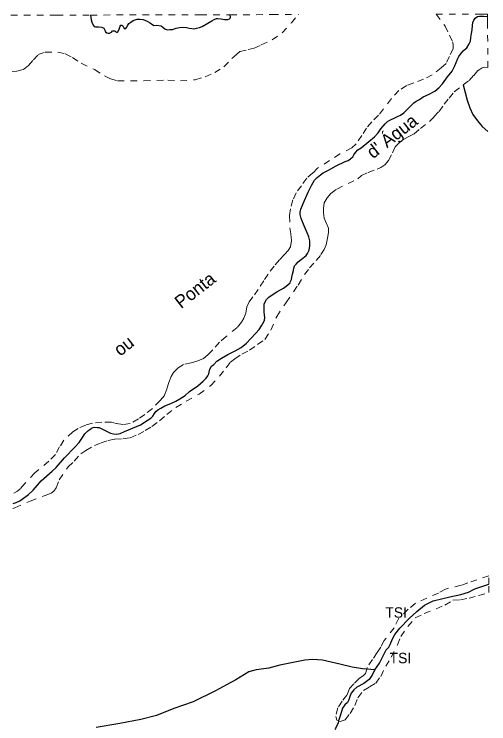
# Model space of a CAD drawing. Extents: x 391.8 to 446, y 8452 to 8507.5.
# Drawn here: x 438.61 to 445.91, y 8496.58 to 8507.5 of the extents above; entities that cross this region are included whole.
import ezdxf
from ezdxf.enums import TextEntityAlignment as Align

# ---------------------------------------------------------------- set-up
doc = ezdxf.new("R2010")
doc.units = 0
doc.header["$LTSCALE"] = 0.064
doc.linetypes.add('LONG_DASHED', pattern=[7.5, 6, -1.5])
doc.linetypes.add('SHORT_DASHED', pattern=[2.7, 1.5, -1.2])
for name, color, linetype, lineweight in [('21', 7, 'SHORT_DASHED', 13), ('62', 7, 'SHORT_DASHED', 13), ('63', 7, 'Continuous', 13), ('7', 7, 'Continuous', 25), ('9', 7, 'LONG_DASHED', 25)]:
    doc.layers.add(name, color=color, linetype=linetype, lineweight=lineweight)
doc.layers.add('61', color=7, linetype='Continuous')

msp = doc.modelspace()

# ---------------------------------------------------------------- linework, layer by layer
at = {"layer": '21'}
for points in [[(438.5766, 8506.6135), (438.6473, 8506.6199), (438.7501, 8506.6456), (438.8273, 8506.7098), (438.9044, 8506.7932), (438.9751, 8506.8767), (439.0844, 8506.9152), (439.2773, 8506.9152), (439.393, 8506.8895), (439.5023, 8506.8317), (439.6373, 8506.7419), (439.843, 8506.6456), (439.9972, 8506.5493), (440.0872, 8506.5043), (440.1965, 8506.4722), (440.6015, 8506.4722), (440.9718, 8506.4832), (441.1646, 8506.4704), (441.3896, 8506.4896), (441.5439, 8506.5346), (441.6918, 8506.5988), (441.8332, 8506.6887), (441.9553, 8506.8171), (442.027, 8506.8772), (442.0784, 8506.9222), (442.207, 8506.9543), (442.297, 8506.9735), (442.4063, 8507.0249), (442.5734, 8507.1019), (442.7277, 8507.2111), (442.8691, 8507.3651), (442.9794, 8507.4914)], [(445.0949, 8507.4959), (445.2327, 8507.3148), (445.2985, 8507.1761), (445.3497, 8507.0739), (445.357, 8507.0374), (445.357, 8506.9644), (445.2985, 8506.8476), (445.2474, 8506.7381), (445.1743, 8506.6724), (445.0354, 8506.5629), (444.9038, 8506.4972), (444.7504, 8506.4389), (444.6407, 8506.4024), (444.5238, 8506.3221), (444.4068, 8506.198), (444.2095, 8505.9425), (444.1072, 8505.8403), (444.0268, 8505.7454), (443.9537, 8505.6286), (443.866, 8505.5045), (443.7993, 8505.4419), (443.6166, 8505.347), (443.4558, 8505.2448), (443.2731, 8505.128), (443.2, 8505.055), (443.105, 8504.9747), (443.0246, 8504.8579), (442.9442, 8504.7484), (442.893, 8504.639), (442.8565, 8504.5003), (442.8419, 8504.3981), (442.8477, 8504.2122), (442.8623, 8504.1173), (442.8696, 8504.0151), (442.855, 8503.9202), (442.8184, 8503.8618), (442.76, 8503.7961), (442.6869, 8503.7158), (442.6065, 8503.621), (442.5115, 8503.4969), (442.4457, 8503.3947), (442.358, 8503.2633), (442.2776, 8503.1465), (442.2191, 8503.0735), (442.1826, 8502.9932), (442.1679, 8502.8983), (442.1387, 8502.818), (442.1022, 8502.7596), (442.0364, 8502.6793), (441.8678, 8502.5371), (441.7655, 8502.4495), (441.6632, 8502.3327), (441.5901, 8502.2597), (441.5097, 8502.194), (441.4147, 8502.1575), (441.327, 8502.1356), (441.21, 8502.1064), (441.1296, 8502.0553), (441.0565, 8501.9823), (441.02, 8501.9239), (440.9834, 8501.8291), (440.9542, 8501.7269), (440.9177, 8501.632), (440.8519, 8501.5517), (440.7318, 8501.4314), (440.6148, 8501.3365), (440.5198, 8501.2708), (440.3883, 8501.1978), (440.2786, 8501.1832), (440.1763, 8501.1978), (440.1032, 8501.2197), (439.957, 8501.2197), (439.8109, 8501.2051), (439.7085, 8501.1759), (439.5916, 8501.1249), (439.5112, 8501.0738), (439.3723, 8500.9424), (439.3065, 8500.8402), (439.2408, 8500.7234), (439.1384, 8500.6212), (438.9265, 8500.4387), (438.7699, 8500.2749), (438.6969, 8500.1946), (438.6603, 8500.1581), (438.6018, 8500.1289)], [(445.5129, 8506.4103), (445.6043, 8506.4779), (445.6729, 8506.5562), (445.7407, 8506.6329), (445.8035, 8506.6747), (445.8465, 8506.6848), (445.8888, 8506.6771)], [(444.1888, 8505.1153), (444.2473, 8505.1372), (444.3057, 8505.1809), (444.3642, 8505.2466), (444.4227, 8505.3634), (444.4665, 8505.4583), (444.5323, 8505.524), (444.5981, 8505.5751), (444.6858, 8505.6189), (444.76, 8505.6585), (444.8551, 8505.7388), (444.9939, 8505.8483), (445.067, 8505.9212), (445.1401, 8506.0015), (445.2205, 8506.111), (445.2936, 8506.2059), (445.374, 8506.3008), (445.5129, 8506.4103)], [(443.4785, 8504.7394), (443.5662, 8504.8051), (443.7416, 8504.8927), (443.8891, 8504.962), (443.9476, 8505.0131), (444.0499, 8505.0642), (444.1888, 8505.1153)], [(438.399, 8499.8303), (438.6182, 8499.9033), (438.8521, 8500.0055), (439.086, 8500.0931), (439.1737, 8500.1296), (439.2176, 8500.1588), (439.2541, 8500.2099), (439.298, 8500.334), (439.4368, 8500.531), (439.5275, 8500.6223), (439.6298, 8500.7318), (439.7102, 8500.7829), (439.8418, 8500.8632), (439.9441, 8500.8997), (440.0537, 8500.9362), (440.156, 8500.9581), (440.2803, 8500.9654), (440.3899, 8500.98), (440.5142, 8501.0311), (440.6238, 8501.0895), (440.7261, 8501.1552), (440.8431, 8501.2428), (440.9527, 8501.3377), (441.0916, 8501.4471), (441.2524, 8501.542), (441.4497, 8501.6515), (441.6324, 8501.7829), (441.764, 8501.9289), (441.8688, 8502.0566), (441.9346, 8502.1442), (442.0003, 8502.1953), (442.11, 8502.2683), (442.2269, 8502.3267), (442.3512, 8502.4142), (442.4608, 8502.4945), (442.5558, 8502.6332), (442.6435, 8502.8449), (442.7897, 8503.0639), (442.9724, 8503.3267), (443.0692, 8503.4912), (443.1496, 8503.5934), (443.2519, 8503.7102), (443.325, 8503.7978), (443.3762, 8503.8781), (443.4054, 8503.9511), (443.4273, 8504.0533), (443.4419, 8504.1409), (443.4419, 8504.2066), (443.4054, 8504.2869), (443.3762, 8504.3599), (443.3615, 8504.4401), (443.3615, 8504.5058), (443.3762, 8504.5934), (443.42, 8504.6737), (443.4785, 8504.7394)], [(445.9047, 8498.8535), (445.7238, 8498.7945), (445.5823, 8498.7503), (445.4817, 8498.7119), (445.2396, 8498.653), (445.1327, 8498.591), (444.9504, 8498.5114), (444.7775, 8498.4348), (444.6643, 8498.3404), (444.5197, 8498.2048), (444.4505, 8498.0544), (444.2964, 8497.8628), (444.2461, 8497.7596), (444.1864, 8497.6741), (444.1172, 8497.5709), (444.0355, 8497.447), (444.0278, 8497.4213)], [(443.5959, 8496.6227), (443.6174, 8496.6126), (443.6991, 8496.6421), (443.7714, 8496.7394), (443.8437, 8496.8603), (443.894, 8496.9812), (443.9789, 8497.0932), (444.0732, 8497.1463), (444.1675, 8497.2053), (444.243, 8497.3085), (444.3216, 8497.4647), (444.4065, 8497.6033), (444.5008, 8497.792), (444.5511, 8497.9217), (444.6611, 8498.0751), (444.7743, 8498.2077), (444.9095, 8498.2756), (445.2302, 8498.4053), (445.3528, 8498.479), (445.4691, 8498.4879), (445.6011, 8498.5114), (445.7489, 8498.5557), (445.9052, 8498.597)], [(444.0278, 8497.4213), (444.0072, 8497.3527), (443.9789, 8497.3202), (443.9129, 8497.276), (443.8311, 8497.1935), (443.762, 8497.1198), (443.7242, 8497.0195), (443.6488, 8496.9281), (443.5859, 8496.8249), (443.5513, 8496.6922), (443.5671, 8496.6362), (443.5959, 8496.6227)]]:
    msp.add_lwpolyline(points, dxfattribs=at)
at = {"layer": '62'}
for p in [(445.0949, 8507.4959), (445.8888, 8506.6771)]:
    msp.add_line(p, (445.8871, 8507.4975), dxfattribs=at)
for points in [[(441.9296, 8507.4892), (442.574, 8507.4906), (442.9794, 8507.4914)], [(437.8375, 8507.48), (438.1565, 8507.4807), (439.2608, 8507.4832), (439.7828, 8507.4844)], [(439.7828, 8507.4844), (441.4696, 8507.4882), (441.9296, 8507.4892)], [(445.9052, 8498.597), (445.9049, 8498.7267), (445.9047, 8498.8535)]]:
    msp.add_lwpolyline(points, dxfattribs=at)
at = {"layer": '63'}
msp.add_lwpolyline([(445.8871, 8507.3743), (445.8871, 8507.4975), (445.7657, 8507.4975)], dxfattribs=at)
at = {"layer": '7'}
for points in [[(439.7828, 8507.4844), (439.791, 8507.4119), (439.8007, 8507.373), (439.8201, 8507.3265), (439.8356, 8507.309), (439.857, 8507.3012), (439.9055, 8507.3012), (439.954, 8507.2993), (439.9869, 8507.2818), (440.0024, 8507.2527), (440.0121, 8507.2236), (440.0296, 8507.21), (440.0509, 8507.2042), (440.0742, 8507.2081), (440.1033, 8507.2197), (440.1169, 8507.2391), (440.1324, 8507.2411), (440.1557, 8507.2411), (440.1693, 8507.2275), (440.179, 8507.2197), (440.1945, 8507.2197), (440.2119, 8507.243), (440.2216, 8507.2682), (440.2391, 8507.3129), (440.2468, 8507.3265), (440.2624, 8507.3284), (440.2779, 8507.3206), (440.2876, 8507.2954), (440.2992, 8507.2799), (440.3108, 8507.2779), (440.3264, 8507.2799), (440.3361, 8507.2915), (440.3555, 8507.3265), (440.369, 8507.3536), (440.402, 8507.3769), (440.4389, 8507.3983), (440.499, 8507.4216), (440.5378, 8507.4235), (440.5882, 8507.4177), (440.6522, 8507.3924), (440.6891, 8507.3711), (440.7201, 8507.3497), (440.7531, 8507.3245), (440.7996, 8507.3265), (440.8695, 8507.3168), (440.8927, 8507.2993), (440.9238, 8507.2741), (440.9587, 8507.2585), (441.0014, 8507.2605), (441.0421, 8507.2644), (441.0964, 8507.2838), (441.1507, 8507.2915), (441.1992, 8507.2993), (441.2555, 8507.2915), (441.2981, 8507.2818), (441.3369, 8507.276), (441.3738, 8507.2741), (441.4106, 8507.2818), (441.4552, 8507.2935), (441.496, 8507.309), (441.5872, 8507.3576), (441.6454, 8507.3964), (441.6803, 8507.4177), (441.7191, 8507.4313), (441.7404, 8507.4313), (441.7889, 8507.4255), (441.8413, 8507.4177), (441.8684, 8507.4158), (441.8917, 8507.4158), (441.9169, 8507.4236), (441.9285, 8507.4352), (441.9344, 8507.4507), (441.9296, 8507.4892)], [(444.1455, 8505.6115), (444.2054, 8505.6731), (444.2472, 8505.733), (444.3094, 8505.8086), (444.3475, 8505.8448), (444.3857, 8505.8684), (444.4601, 8505.901), (444.5037, 8505.921), (444.5473, 8505.9446), (444.5963, 8505.979), (444.638, 8506.0189), (444.727, 8506.1059), (444.7532, 8506.1325), (444.7895, 8506.1578), (444.8385, 8506.1868), (444.8984, 8506.2249), (444.9783, 8506.2612), (445.0746, 8506.3156), (445.1363, 8506.3645), (445.1926, 8506.4244), (445.2725, 8506.5314), (445.3421, 8506.6231), (445.3766, 8506.6902), (445.4038, 8506.7537), (445.4274, 8506.8172), (445.442, 8506.8444), (445.4692, 8506.8843), (445.511, 8506.9314), (445.5654, 8506.9785), (445.6058, 8507.0432), (445.624, 8507.0849), (445.6312, 8507.1375), (445.6403, 8507.2028), (445.6494, 8507.2572), (445.6567, 8507.3224), (445.6621, 8507.3678), (445.6766, 8507.4077), (445.6971, 8507.4379), (445.7298, 8507.4596), (445.7615, 8507.4671), (445.823, 8507.4667), (445.8871, 8507.4596)], [(443.815, 8505.3032), (443.8295, 8505.3358), (443.8532, 8505.3703), (443.8895, 8505.4084), (443.9403, 8505.441), (444.062, 8505.5389), (444.1455, 8505.6115)], [(439.8451, 8501.1422), (439.8814, 8501.1404), (439.9122, 8501.1368), (439.9359, 8501.1295), (439.9976, 8501.0969), (440.0866, 8501.0516), (440.1338, 8501.0389), (440.1837, 8501.0353), (440.2382, 8501.0462), (440.3054, 8501.0752), (440.4252, 8501.126), (440.5505, 8501.1786), (440.654, 8501.2475), (440.7075, 8501.2828), (440.7402, 8501.3136), (440.7638, 8501.3517), (440.7874, 8501.3844), (440.8182, 8501.4116), (440.86, 8501.437), (440.9254, 8501.4714), (441.0162, 8501.5059), (441.093, 8501.5431), (441.1566, 8501.5775), (441.2365, 8501.6301), (441.3055, 8501.6899), (441.4308, 8501.7788), (441.5143, 8501.8513), (441.56, 8501.8994), (441.5854, 8501.932), (441.5981, 8501.9628), (441.6054, 8501.9882), (441.6181, 8502.0335), (441.6435, 8502.0807), (441.6762, 8502.1097), (441.7252, 8502.1569), (441.796, 8502.204), (441.8941, 8502.262), (442.0038, 8502.3161), (442.0964, 8502.3705), (442.1818, 8502.434), (442.2453, 8502.5083), (442.3234, 8502.5917), (442.3724, 8502.6461), (442.4124, 8502.7005), (442.4324, 8502.7386), (442.456, 8502.7821), (442.4602, 8502.8304), (442.4529, 8502.912), (442.4511, 8502.9809), (442.4511, 8503.0353), (442.4602, 8503.0625), (442.4892, 8503.1097), (442.5237, 8503.1441), (442.5727, 8503.1786), (442.6472, 8503.2257), (442.747, 8503.2801), (442.7911, 8503.314), (442.8201, 8503.3376), (442.8492, 8503.3648), (442.8583, 8503.3848), (442.8691, 8503.4174), (442.8764, 8503.45), (442.8873, 8503.499), (442.9, 8503.5516), (442.9055, 8503.5897), (442.92, 8503.6259), (442.9436, 8503.6513), (442.9763, 8503.6894), (443.018, 8503.722), (443.0947, 8503.7851), (443.1164, 8503.8159), (443.1419, 8503.8685), (443.1546, 8503.9338), (443.1509, 8504.0081), (443.1401, 8504.0716), (443.1128, 8504.1333), (443.0638, 8504.2403), (443.0219, 8504.3524), (443.0073, 8504.4159), (443.0037, 8504.4521), (443.0146, 8504.4957), (443.0491, 8504.5845), (443.1253, 8504.7568), (443.1818, 8504.8705), (443.2236, 8504.9412), (443.2653, 8504.9847), (443.3162, 8505.0246), (443.3598, 8505.0554), (443.4397, 8505.0953), (443.5559, 8505.166), (443.6993, 8505.2295), (443.7424, 8505.2488), (443.7769, 8505.2705), (443.7914, 8505.2814), (443.815, 8505.3032)], [(439.6453, 8500.9681), (439.6962, 8501.0425), (439.7398, 8501.0878), (439.7688, 8501.1096), (439.7942, 8501.1259), (439.8196, 8501.1386), (439.8451, 8501.1422)], [(438.594, 8499.9664), (438.6394, 8499.9845), (438.6921, 8500.0117), (438.732, 8500.0335), (438.8265, 8500.1078), (438.8982, 8500.1718), (438.9654, 8500.2516), (439.0235, 8500.3187), (439.1894, 8500.4667), (439.253, 8500.5211), (439.3819, 8500.6717), (439.5398, 8500.833), (439.6072, 8500.9065), (439.6453, 8500.9681)], [(444.1526, 8497.4115), (444.2267, 8497.5122), (444.3262, 8497.7161), (444.3681, 8497.7579), (444.3891, 8497.7998), (444.4257, 8497.8887), (444.4624, 8497.9514), (444.5357, 8498.0508), (444.6823, 8498.1972), (444.7975, 8498.3071), (444.918, 8498.4064), (445.0489, 8498.4692), (445.3055, 8498.5319), (445.474, 8498.5699), (445.5944, 8498.6065), (445.6887, 8498.6536), (445.9049, 8498.7267), (445.9053, 8498.7268)], [(444.1526, 8497.4115), (444.1056, 8497.3198), (444.0637, 8497.2623), (443.9852, 8497.1995), (443.8752, 8497.142), (443.8281, 8497.1002), (443.7914, 8497.0479), (443.7705, 8497.0008), (443.7548, 8496.9485), (443.7338, 8496.9067), (443.692, 8496.8701), (443.6553, 8496.8178), (443.6239, 8496.7184), (443.5959, 8496.6227)], [(443.5959, 8496.6227), (443.5872, 8496.5929), (443.5506, 8496.5092), (443.5392, 8496.4926)]]:
    msp.add_lwpolyline(points, dxfattribs=at)
at = {"layer": '9'}
msp.add_line((444.1526, 8497.4115), (444.0278, 8497.4213), dxfattribs=at)
for points in [[(445.5129, 8506.4103), (445.5732, 8506.1726), (445.6134, 8506.0556), (445.6603, 8505.9552), (445.7306, 8505.8549), (445.8043, 8505.7679), (445.8914, 8505.6943)], [(444.0278, 8497.4213), (443.9635, 8497.4264), (443.8042, 8497.4513), (443.6151, 8497.496), (443.3464, 8497.5557), (443.1922, 8497.5706), (443.0777, 8497.5606), (442.9483, 8497.5308), (442.6896, 8497.4811), (442.5211, 8497.4341), (442.3266, 8497.4075), (442.2146, 8497.3791), (442.0178, 8497.2575), (441.8709, 8497.1807), (441.7038, 8497.0855), (441.3583, 8496.9173), (441.0598, 8496.8129), (440.796, 8496.7086), (440.5572, 8496.644), (440.2337, 8496.5843), (439.8675, 8496.5225)]]:
    msp.add_lwpolyline(points, dxfattribs=at)

# ---------------------------------------------------------------- texts
at = {"layer": '61'}
msp.add_text("Veredão                                                  ou            Ponta                                         d' Água", height=0.2, rotation=38.012, dxfattribs=at).set_placement((440.6725, 8502.5665), align=Align.CENTER)
for p in [(444.4804, 8498.2119), (444.5463, 8497.5112)]:
    msp.add_text('TSI', height=0.16, dxfattribs=at).set_placement(p, align=Align.CENTER)

doc.saveas('drawing.dxf')
